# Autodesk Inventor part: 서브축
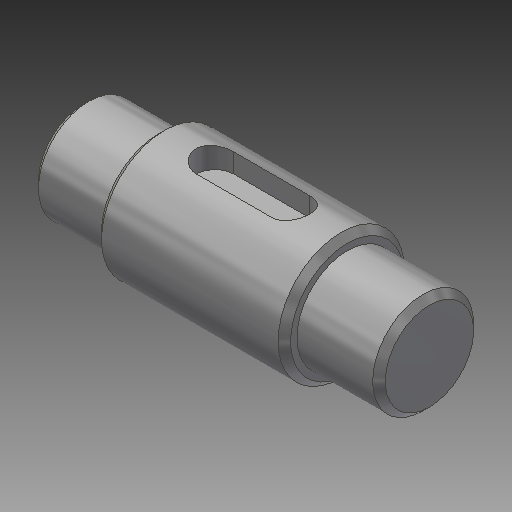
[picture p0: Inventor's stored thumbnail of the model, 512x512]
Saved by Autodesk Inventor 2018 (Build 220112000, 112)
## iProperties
Created: 2019-03
Part Number: 서브축
Material: 강철, 연강
Document SubType Name: Modeling
Designer: mduedu
Density: 1 g/cm^3
Appearance: 강철
Author: mduedu
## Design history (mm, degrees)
sketch "스케치1"
  geometry: L1 (0, 0)-(12, 0); L2 (12, 0)-(12, 8); L3 (12, 8)-(0, 8); L4 (0, 8)-(0, 0); L5 (12, 0)-(42, 0); L6 (42, 0)-(42, 10); L7 (42, 10)-(12, 10); L8 (12, 10)-(12, 0); L9 (42, 0)-(55, 0); L10 (55, 0)-(55, 8); L11 (55, 8)-(42, 8); L12 (42, 8)-(42, 0)
  constraints: 24 end point, 6 parallel, 3 horizontal, 3 perpendicular
  dimensions: "d0" = 16 diameter of L3 L1; "d2" = 20 diameter of L7 L5; "d3" = 16 diameter of L11 L9; "d4" = 12 distance of L2.end L3.end; "d5" = 30 distance of L6.end L7.end; "d6" = 55 distance between parallel lines of L10 L4
revolve "회전1" sketch "스케치1" stored, may be unused: angle "d7" = 90 deg
node "작업 평면1"
sketch "스케치2" dims "d10" = 18
  geometry: L1 (6, -3)-(-6, -3); L2 (-6, -3)-(-6, 3); L3 (-6, 3)-(6, 3); L4 (6, 3)-(6, -3); L5 (15, 10)-(15, -10) reference; 3 further points
  constraints: 8 end point, 2 midpoint, 2 parallel, 2 vertical alignment, 1 horizontal, 1 horizontal alignment, 1 perpendicular, 4 other
  dimensions: "d8" = 6 distance between parallel lines of L3 L1; "d11" = 6 dimension on L5
extrude "돌출1" cut sketch "스케치2" distance "d12" = 3.5; taper "d13" = 0 deg
chamfer "모따기1" distance "d14" = 1; stored, may be unused: second distance "d15" = 2, angle "d16" = 45 deg
chamfer "모따기2" distance "d17" = 1; stored, may be unused: second distance "d18" = 2, angle "d19" = 45 deg
node "솔리드1"
